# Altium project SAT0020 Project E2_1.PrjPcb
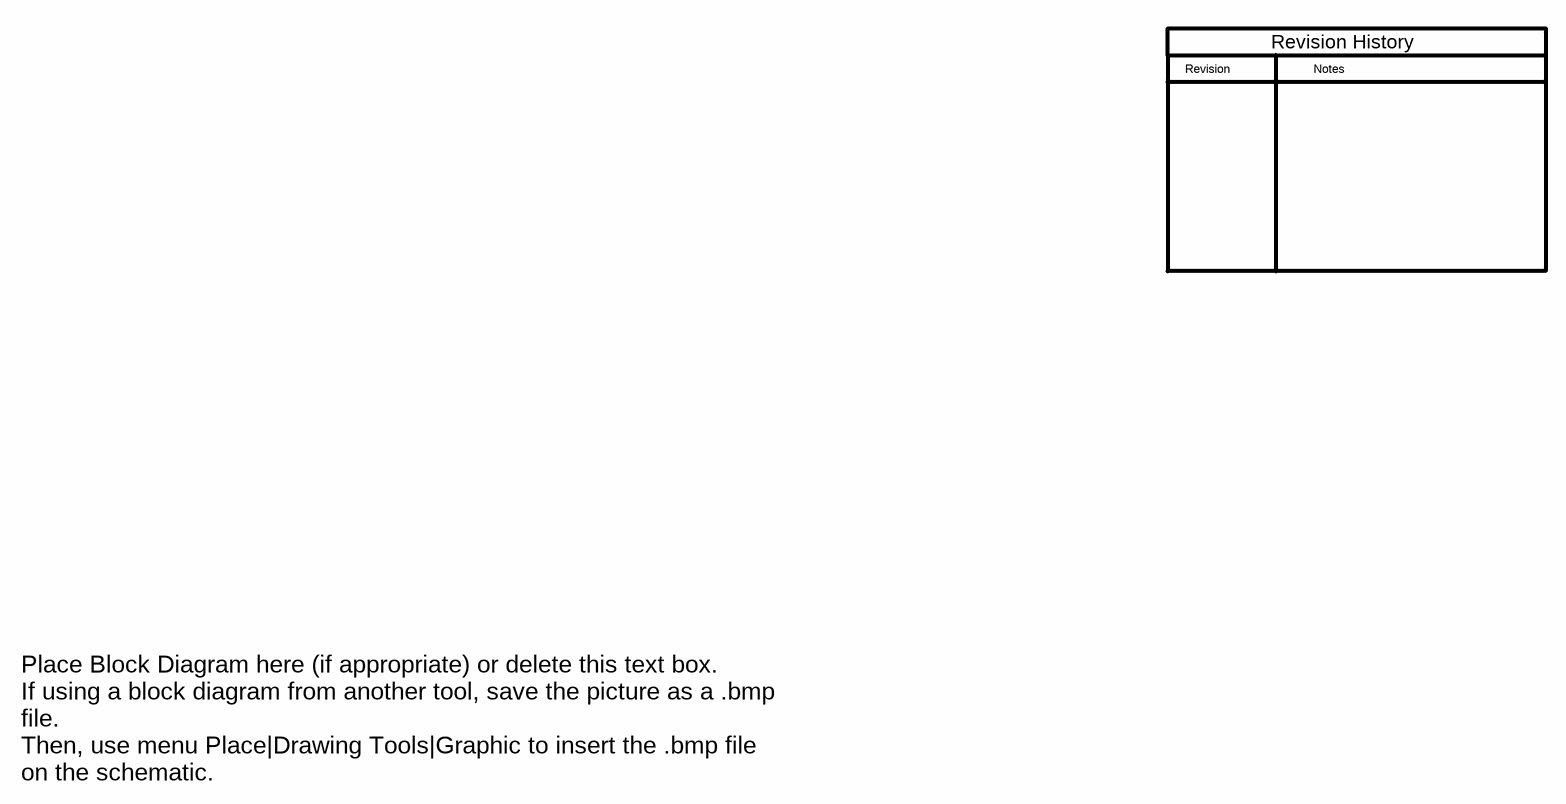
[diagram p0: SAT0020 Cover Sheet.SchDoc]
CopyrightYear: 2014; PCB_Layout: Ian Cathey; PCB_Rev: E2.0; PRJ_Customer: Public Release; PRJ_Engineer: Ian Cathey; PRJ_Number: SAT0020; PRJ_Title: Piezoelectric Air Flow Sensor; SCH_Rev: E2.0; TechSupport: http://www.ti.com/support
3 sheets, 66 parts. Net scope: global (net labels, ports and power ports of the same name join across sheets).
Board file: SAT0020 PCB E2_1.PcbDoc
Sheets:
  SAT0020 Cover Sheet.SchDoc
  SAT0020 Sheet1.SchDoc
  Hardware_ANSI-B.SchDoc

## Sheet SAT0020 Cover Sheet.SchDoc
size 431 x 279 mm; Date: Not shown in title block; ApprovedBy: Not shown in title block; CheckedBy: Not shown in title block; Author: Not shown in title block; CompanyName: Not shown in title block; Engineer: Not shown in title block; Organization: Not shown in title block; Address1: Not shown in title block; Address2: Not shown in title block; Address3: Not shown in title block; Address4: Not shown in title block; DocumentNumber: 3; Revision: Use project parameter SCH_Rev; SheetNumber: 3; SheetTotal: 3; PageSetup: Record=PageOptions|CenterHorizontal=True|CenterVertical=True|PrintScale=1.00|XCorrection=1.00|YCorrection=1.00|PrintKind=0|BorderSize=5000000|LeftOffset=0|BottomOffset=0|Orientation=2|PaperLength=1000|PaperWidth=1000|Scale=100|PaperSource=15|PrintQuality=600|MediaType=1|DitherType=10|PaperKind=Letter|PrintScaleMode=1

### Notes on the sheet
- Revision
- Notes
- Revision History
- Place Block Diagram here (if appropriate) or delete this text box.
  If using a block diagram from another tool, save the picture as a .bmp file.
  Then, use menu Place|Drawing Tools|Graphic to insert the .bmp file on the schematic.

## Sheet SAT0020 Sheet1.SchDoc
size 431 x 279 mm; Date: Not shown in title block; ApprovedBy: Not shown in title block; CheckedBy: Not shown in title block; Author: Not shown in title block; CompanyName: Not shown in title block; DrawnBy: Ian Cathey; Engineer: Not shown in title block; Organization: Not shown in title block; Address1: Not shown in title block; Address2: Not shown in title block; Address3: Not shown in title block; Address4: Not shown in title block; DocumentNumber: 1; Revision: Use project parameter SCH_Rev; SheetNumber: 1; SheetTotal: 3; PageSetup: Record=PageOptions|CenterHorizontal=True|CenterVertical=True|PrintScale=0.96|XCorrection=1.00|YCorrection=1.00|PrintKind=0|BorderSize=5000000|LeftOffset=0|BottomOffset=0|Orientation=2|PaperLength=1000|PaperWidth=1000|Scale=100|PaperSource=15|PrintQuality=600|MediaType=1|DitherType=10|PaperKind=11x17|PrintScaleMode=1
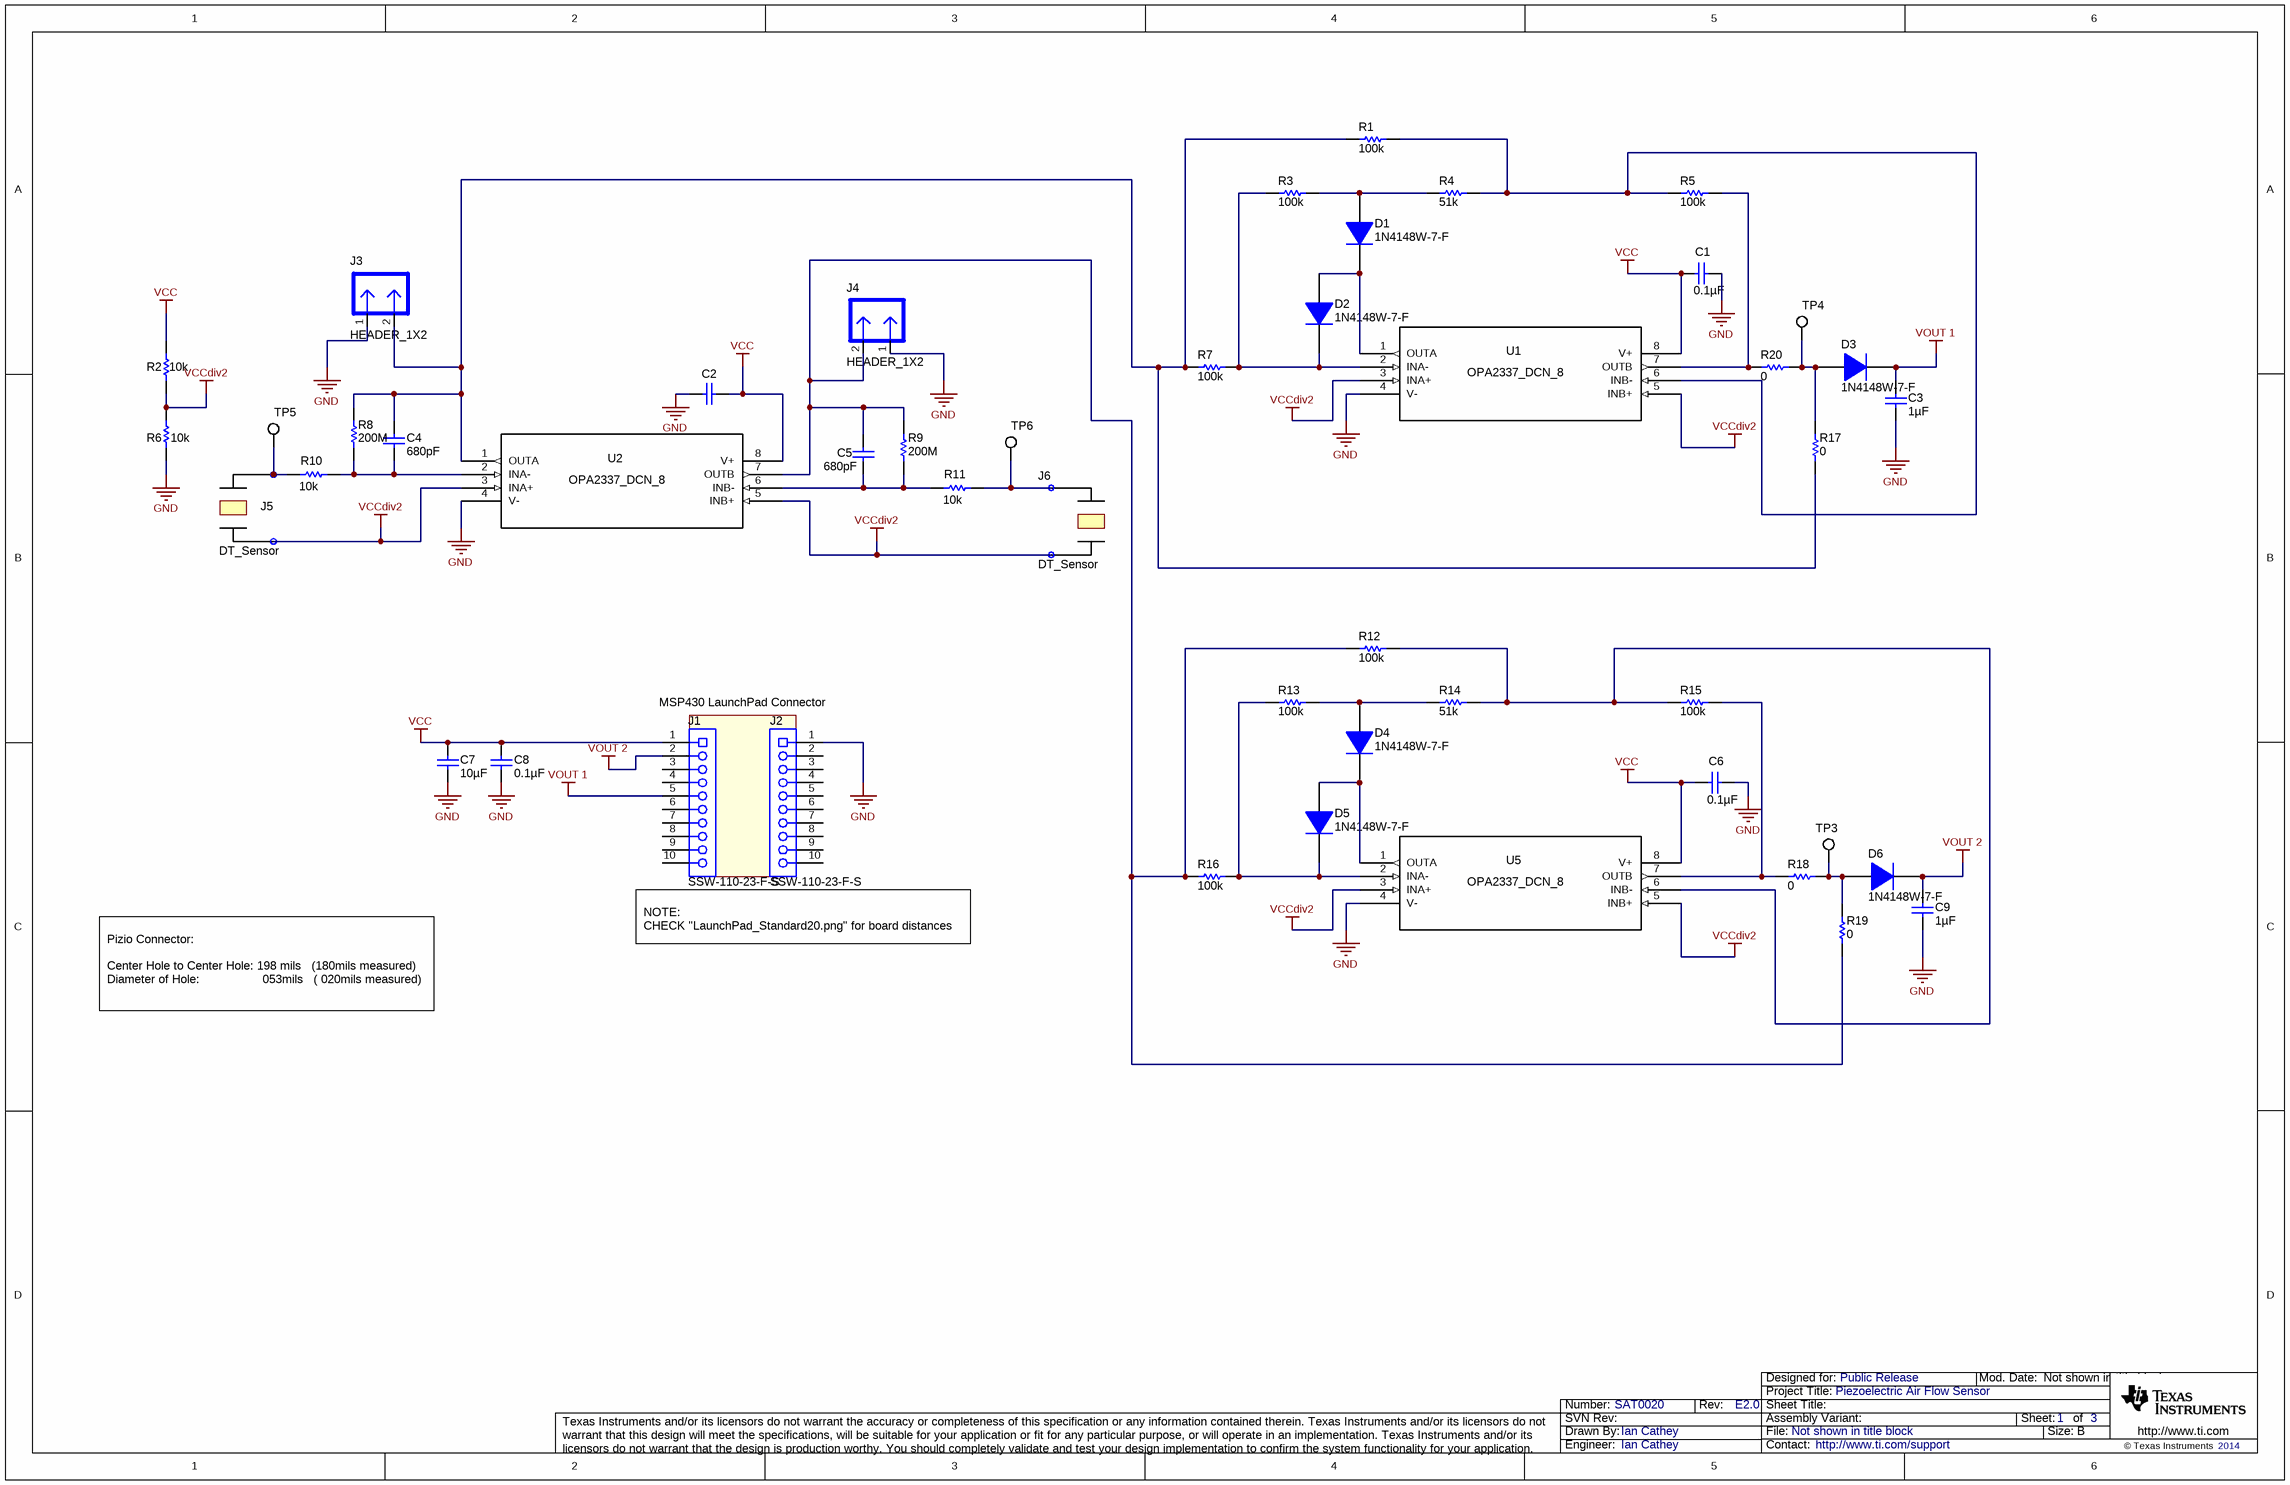
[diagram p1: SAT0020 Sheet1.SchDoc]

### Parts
C1  ValueDisplayed: 0.1µF  [0603]  (hidden comment: 06033C104KAT2A)
C2  06033C104KAT2A  [0603]  (value not drawn)
C3  ValueDisplayed: 1µF  [0603]  (hidden comment: C1608X5R0J105K)
C4  ValueDisplayed: 680pF  [0603]  (hidden comment: C0603C681K5RACTU)
C5  ValueDisplayed: 680pF  [0603]  (hidden comment: C0603C681K5RACTU)
C6  ValueDisplayed: 0.1µF  [0603]  (hidden comment: 06033C104KAT2A)
C7  ValueDisplayed: 10µF  [0603]  (hidden comment: GRM188R60J106ME47D)
C8  ValueDisplayed: 0.1µF  [0603]  (hidden comment: 06033C104KAT2A)
C9  ValueDisplayed: 1µF  [0603]  (hidden comment: C1608X5R0J105K)
D1  1N4148W-7-F  [SOD-123]
D2  1N4148W-7-F  [SOD-123]
D3  1N4148W-7-F  [SOD-123]
D4  1N4148W-7-F  [SOD-123]
D5  1N4148W-7-F  [SOD-123]
D6  1N4148W-7-F  [SOD-123]
J1  SSW-110-23-F-S  [CONN_SSW-110-23-F-S]
J2  SSW-110-23-F-S  [CONN_SSW-110-23-F-S]
J3  HEADER_1X2  [HDR100_1X2]
J4  HEADER_1X2  [HDR100_1X2]
J5  DT_Sensor  [DT_Sensor]
J6  DT_Sensor  [DT_Sensor]
R1  value 100k  [0603]  (hidden comment: CRCW0603100KFKEA)
R2  value 10k  [0603]  (hidden comment: CRCW060310K0JNEA)
R3  value 100k  [0603]  (hidden comment: CRCW0603100KFKEA)
R4  value 51k  [0603]  (hidden comment: CRCW060351K0JNEA)
R5  value 100k  [0603]  (hidden comment: CRCW0603100KFKEA)
R6  value 10k  [0603]  (hidden comment: CRCW060310K0JNEA)
R7  value 100k  [0603]  (hidden comment: CRCW0603100KFKEA)
R8  value 200M  [0603]  (hidden comment: CRCW0603200MJPEAHR)
R9  value 200M  [0603]  (hidden comment: CRCW0603200MJPEAHR)
R10  value 10k  [0603]  (hidden comment: CRCW060310K0JNEA)
R11  value 10k  [0603]  (hidden comment: CRCW060310K0JNEA)
R12  value 100k  [0603]  (hidden comment: CRCW0603100KFKEA)
R13  value 100k  [0603]  (hidden comment: CRCW0603100KFKEA)
R14  value 51k  [0603]  (hidden comment: CRCW060351K0JNEA)
R15  value 100k  [0603]  (hidden comment: CRCW0603100KFKEA)
R16  value 100k  [0603]  (hidden comment: CRCW0603100KFKEA)
R17  value 0  [0603]  (hidden comment: CRCW06030000Z0EA)
R18  value 0  [0603]  (hidden comment: CRCW06030000Z0EA)
R19  value 0  [0603]  (hidden comment: CRCW06030000Z0EA)
R20  value 0  [0603]  (hidden comment: CRCW06030000Z0EA)
TP3  5002  [Keystone5002]  (value not drawn)
TP4  5002  [Keystone5002]  (value not drawn)
TP5  5002  [Keystone5002]  (value not drawn)
TP6  5002  [Keystone5002]  (value not drawn)
U1  OPA2337_DCN_8  [DCN8]
U2  OPA2337_DCN_8  [DCN8]
U5  OPA2337_DCN_8  [DCN8]

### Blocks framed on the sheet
MSP430 LaunchPad Connector: J1

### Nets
GND: C1.1 C2.2 C3.2 C6.1 C7.2 C8.1 C9.2 J2.1 J3.1 J4.1 R6.1 U1.4(V-) U2.4(V-) U5.4(V-)
VCC: C1.2 C2.1 C6.2 C7.1 C8.2 J1.1 R2.2 U1.8(V+) U2.8(V+) U5.8(V+)
VCCdiv2: J5.2 J6.2 R2.1 R6.2 U1.3(INA+) U1.5(INB+) U2.3(INA+) U2.5(INB+) U5.3(INA+) U5.5(INB+)
VOUT 1: C3.1 D3.1(K) J1.5
VOUT 2: C9.1 D6.1(K) J1.2
NetC4_1: C4.1 J3.2 R1.1 R7.1 R8.2 R17.1 U2.1(OUTA)
NetC4_2: C4.2 R8.1 R10.1 U2.2(INA-)
NetC5_1: C5.1 J4.2 R9.2 R12.1 R16.1 R19.1 U2.7(OUTB)
NetC5_2: C5.2 R9.1 R11.2 U2.6(INB-)
NetD1_1: D1.1(K) D2.2(A) U1.1(OUTA)
NetD1_2: D1.2(A) R3.2 R4.1
NetD2_1: D2.1(K) R3.1 R7.2 U1.2(INA-)
NetD3_2: D3.2(A) R17.2 R20.1 TP4.1
NetD4_1: D4.1(K) D5.2(A) U5.1(OUTA)
NetD4_2: D4.2(A) R13.2 R14.1
NetD5_1: D5.1(K) R13.1 R16.2 U5.2(INA-)
NetD6_2: D6.2(A) R18.1 R19.2 TP3.1
NetJ5_1: J5.1 R10.2 TP5.1
NetJ6_1: J6.1 R11.1 TP6.1
NetR1_2: R1.2 R4.2 R5.1 U1.6(INB-)
NetR5_2: R5.2 R20.2 U1.7(OUTB)
NetR12_2: R12.2 R14.2 R15.1 U5.6(INB-)
NetR15_2: R15.2 R18.2 U5.7(OUTB)

Not connected (* = marked no-connect by the designer): J1 3 4 6 7 8 9 10; J2 2 3 4 5 6 7 8 9 10

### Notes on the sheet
- NOTE:
  CHECK "LaunchPad_Standard20.png" for board distances
- Pizio Connector:
  Center Hole to Center Hole: 198 mils   (180mils measured)
  Diameter of Hole:                  053mils   ( 020mils measured)

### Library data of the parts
C1 C2 C6 C8 = 06033C104KAT2A: CAP, CERM, 0.1uF, 25V, +/-10%, X7R, 0603; Manufacturer: AVX; Polarized: N; CompType: Capacitor; U/M: EA; Cap_F: 0.0000001; Tolerance_%: 10; ESR_Ohm: 0.05; Value1: 0.05 ohm; VDC_V: 25; TaMin_C: -55; TaMax_C: 125
C3 C9 = C1608X5R0J105K: CAP, CERM, 1uF, 6.3V, +/-10%, X5R, 0603; Manufacturer: TDK; Polarized: N; CompType: Capacitor; U/M: EA; Cap_F: 0.000001; Tolerance_%: 10; ESR_Ohm: 0.0057; Value1: 0.0057 ohm; VDC_V: 6.3; TaMin_C: -55; TaMax_C: 85
C4 C5 = C0603C681K5RACTU: CAP, CERM, 680pF, 50V, +/-10%, X7R, 0603; Manufacturer: Kemet; Polarized: N; CompType: Capacitor; U/M: EA; Cap_F: 0.00000000068; Tolerance_%: 10; Value1: Unknown; VDC_V: 50; TaMin_C: -55; TaMax_C: 125
C7 = GRM188R60J106ME47D: CAP, CERM, 10uF, 6.3V, +/-20%, X5R, 0603; Manufacturer: MuRata; Polarized: N; CompType: Capacitor; U/M: EA; Cap_F: 0.00001; Tolerance_%: 20; ESR_Ohm: 0.009; Value1: 0.009 ohm; VDC_V: 6.3; IRMS_A: 2.74; TaMin_C: -55; TaMax_C: 125
D1-D6 = 1N4148W-7-F: Diode, Ultrafast, 100V, 0.15A, SOD-123; Manufacturer: Diodes Inc.; U/M: EA; Vf_V: 1.25; Value2: 1.25V; Io_A: 0.15; Vr_V: 100; TJmax_C: 150
J1 J2 = SSW-110-23-F-S: Connector, Receptacle, 100mil, 10x1, Gold plated, TH; Manufacturer: Samtec; SymbolCreator: a0411947; U/M: EA
J3 J4 = HEADER_1X2: Header, Male 2-pin, 100mil spacing,; Manufacturer: Sullins; PartNumber: PEC02SAAN; area: 20000; Value: PEC02SAAN
J5 J6 = Component_1: Manufacturer: Used in BOM report; SymbolVersion: use current date i.e. 2008-05-20; SymbolCreator: Use a-id; CompType: Used in some BOM reports.  Useful for finding later.; U/M: EA, IN, or GM
R1 R3 R5 R7 R12 R13 R15 R16 = CRCW0603100KFKEA: RES, 100k ohm, 1%, 0.1W, 0603; Manufacturer: Vishay-Dale; CompType: Resistor; Res_ohm: 100000; Tolerance_%: 1; Power_W: 0.1; VDC_V: 75; TempCo: 100 ppm/C; EIA_Code: E96; U/M: EA
R2 R6 R10 R11 = CRCW060310K0JNEA: RES, 10k ohm, 5%, 0.1W, 0603; Manufacturer: Vishay-Dale; CompType: Resistor; Res_ohm: 10000; Value_Code: 10k0; Tolerance_%: 5; Power_W: 0.1; VDC_V: 75; TempCo: 200 ppm/C; EIA_Code: E24; U/M: EA
R4 R14 = CRCW060351K0JNEA: RES, 51k ohm, 5%, 0.1W, 0603; Manufacturer: Vishay-Dale; CompType: Resistor; Res_ohm: 51000; Value_Code: 51k0; Tolerance_%: 5; Power_W: 0.1; VDC_V: 75; TempCo: 200 ppm/C; EIA_Code: E24; U/M: EA
R8 R9 = CRCW0603200KJNEA: RES, 200M ohm, 5%, 0.1W, 0603; Manufacturer: Vishay-Dale; CompType: Resistor; Res_ohm: 200000000; Tolerance_%: 5; Power_W: 0.1; VDC_V: 75; TempCo: 500 ppm/C; U/M: EA
R17-R20 = CRCW06030000Z0EA: RES, 0 ohm, 5%, 0.1W, 0603; Manufacturer: Vishay-Dale; CompType: Resistor; Value_Code: 0000; Tolerance_%: 5; Power_W: 0.1; VDC_V: 75; TempCo: 200 ppm/C; EIA_Code: E24; U/M: EA
TP3-TP6 = 5002: Test Point, TH, Miniature, White; Manufacturer: Keystone; Alternate Manufacturer: Any; Alternate PartNumber: Equivalent; CompType: Test Point Loop; U/M: EA
U1 U2 U5 = OPA2337_DCN_8: Imported; Manufacturer: Texas Instruments; INDUSTRY_STD_PKG_TYPE: SOT-23; FAMILY_NAME: LOW INPUT BIAS CURRENT/FET INPUT; PIN_COUNT: 8; PACKAGE_DESIGNATOR: DCN

## Sheet Hardware_ANSI-B.SchDoc
size 431 x 279 mm; Date: Not shown in title block; ApprovedBy: Not shown in title block; CheckedBy: Not shown in title block; Author: Not shown in title block; CompanyName: Not shown in title block; Engineer: Not shown in title block; Organization: Not shown in title block; Address1: Not shown in title block; Address2: Not shown in title block; Address3: Not shown in title block; Address4: Not shown in title block; DocumentNumber: 2; Revision: Use project parameter SCH_Rev; SheetNumber: 2; SheetTotal: 3; PageSetup: Record=PageOptions|CenterHorizontal=True|CenterVertical=True|PrintScale=1.00|XCorrection=1.00|YCorrection=1.00|PrintKind=0|BorderSize=5000000|LeftOffset=0|BottomOffset=0|Orientation=2|PaperLength=1000|PaperWidth=1000|Scale=100|PaperSource=15|PrintQuality=600|MediaType=1|DitherType=10|PaperKind=Letter|PrintScaleMode=1
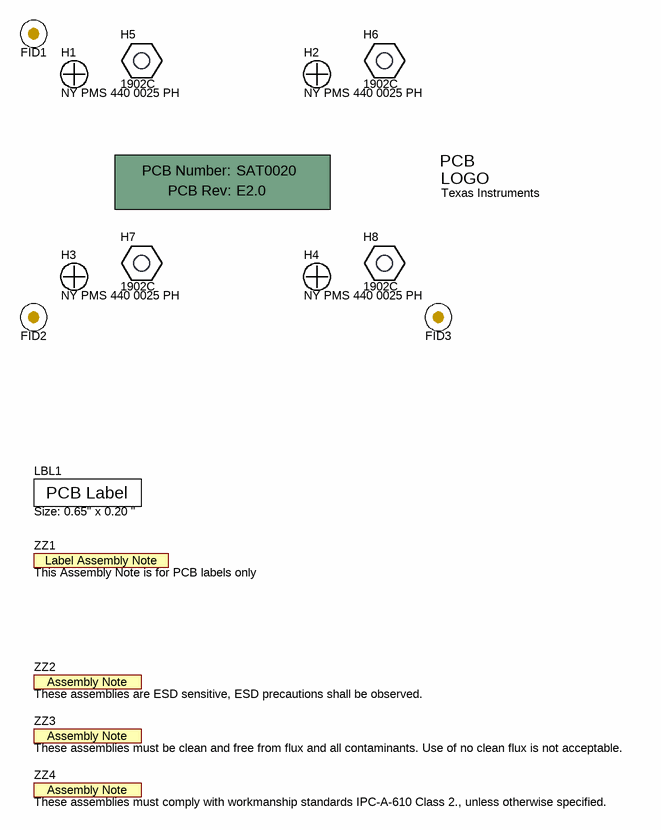
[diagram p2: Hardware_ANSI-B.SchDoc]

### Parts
!PCB  Printed Circuit Board  (value not drawn)  (mechanical)
FID1  Fiducial  [Fiducial10-20]  (value not drawn)
FID2  Fiducial  [Fiducial10-20]  (value not drawn)
FID3  Fiducial  [Fiducial10-20]  (value not drawn)
H1  NY PMS 440 0025 PH  [NY PMS 440 0025 PH]
H2  NY PMS 440 0025 PH  [NY PMS 440 0025 PH]
H3  NY PMS 440 0025 PH  [NY PMS 440 0025 PH]
H4  NY PMS 440 0025 PH  [NY PMS 440 0025 PH]
H5  1902C  [Keystone_1902C]
H6  1902C  [Keystone_1902C]
H7  1902C  [Keystone_1902C]
H8  1902C  [Keystone_1902C]
LBL1  Size: 0.65" x 0.20 "  [Label_650x200]
Logo1  Texas Instruments  [TI_Stacked_SolderMask_Small]  (no BOM)
ZZ1  This Assembly Note is for PCB labels only  [AssemblyNoteLabel]  (no BOM)
ZZ2  These assemblies are ESD sensitive, ESD precautions shall be observed.  [AssemblyNote]  (no BOM)
ZZ3  These assemblies must be clean and free from flux and all contaminants. Use of no clean flux is not acceptable.  [AssemblyNote]  (no BOM)
ZZ4  These assemblies must comply with workmanship standards IPC-A-610 Class 2., unless otherwise specified.  [AssemblyNote]  (no BOM)

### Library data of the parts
!PCB = PCB: Manufacturer: Any; PartNumber: SAT0020; SymbolCreator: a0412235
FID1-FID3 = Fiducial: Fiducial mark.  There is nothing to buy or mount.; SymbolCreator: codlsc
H1-H4 = NY PMS 440 0025 PH: Machine Screw, Round, #4-40 x 1/4, Nylon, Philips panhead; Manufacturer: B&F Fastener Supply; CompType: Hardware; SymbolCreator: codlsc; U/M: EA
H5-H8 = 1902C: Standoff, Hex, 0.5"L #4-40 Nylon; Manufacturer: Keystone; CompType: Hardware
LBL1 = THT-14-423-10: Thermal Transfer Printable Labels, 0.650" W x 0.200" H - 10,000 per roll; Manufacturer: Brady; SymbolCreator: a0412235; CompType: Label
Logo1 = TI_Logo: Texas Instrument Corporate Signature; SymbolCreator: codlsc
ZZ1 = AssemblyNoteLabel: SymbolCreator: a0412235
ZZ2-ZZ4 = AssemblyNote: SymbolCreator: codlsc

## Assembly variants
001: not fitted J5 J6 R17 R19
